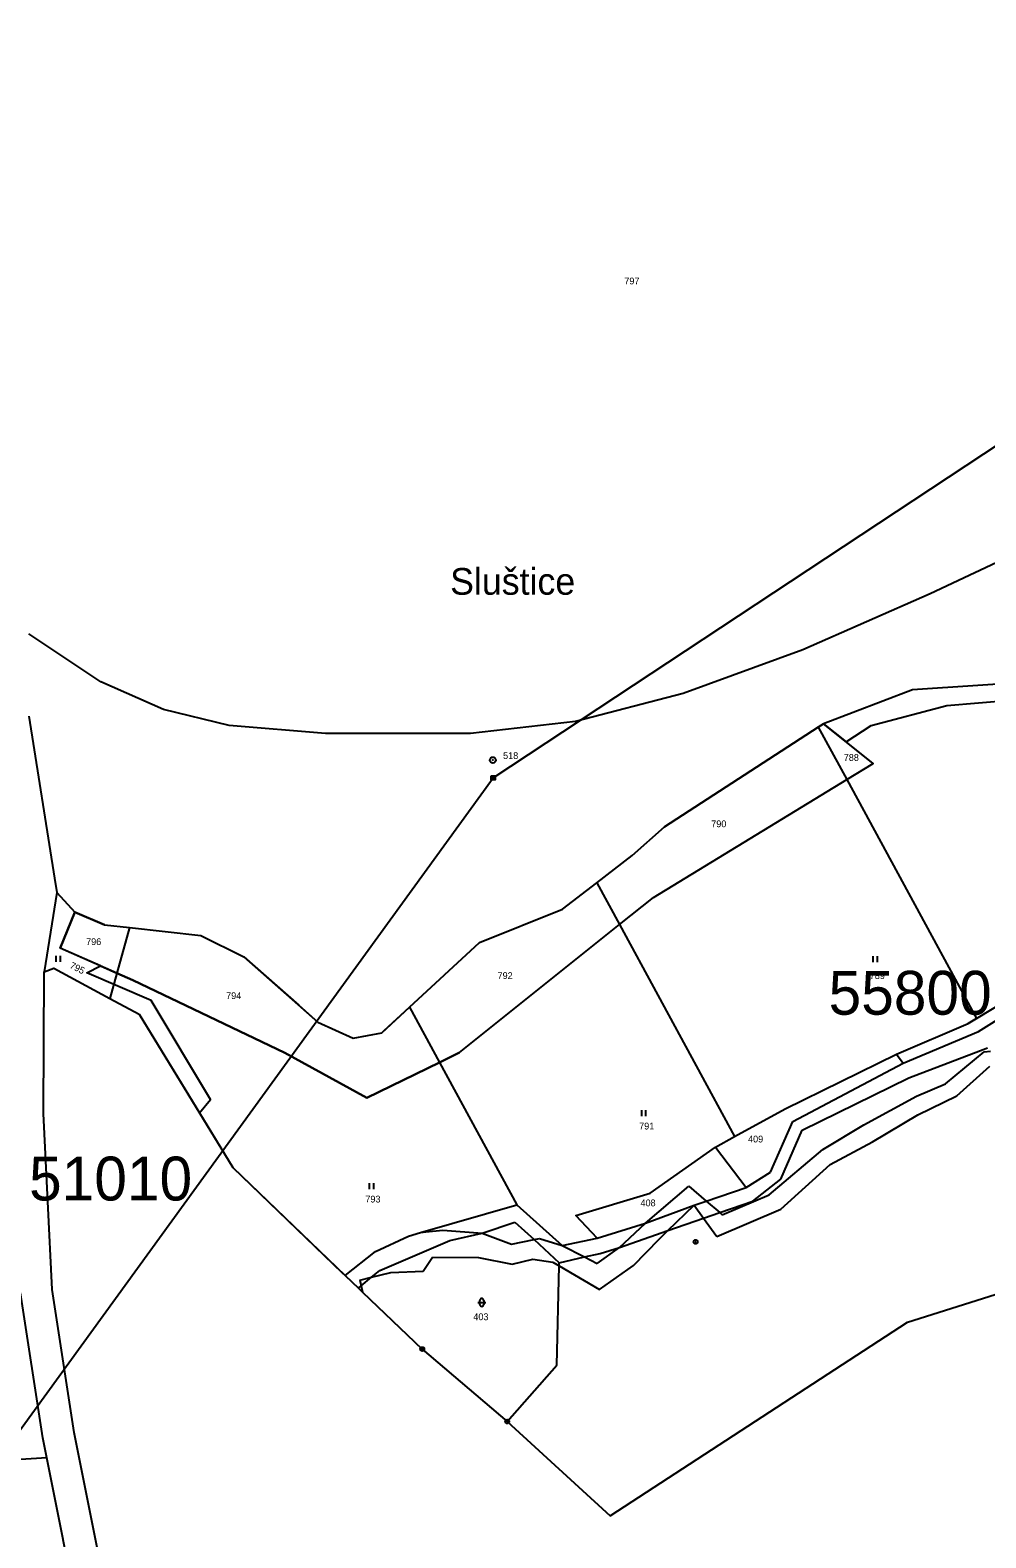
# Model space of a CAD drawing. Extents: x -725765 to -723182, y -1052705 to -1049154.
# Drawn here: x -724181.6 to -723941.9, y -1052292.7 to -1051914.6 of the extents above; entities that cross this region are included whole.
import ezdxf

# ---------------------------------------------------------------- set-up
doc = ezdxf.new("R2010")
doc.units = 0
for name, color, linetype in [('Vrstva 1', 7, 'Continuous'), ('Vrstva 12', 7, 'Continuous'), ('Vrstva 13', 7, 'Continuous'), ('Vrstva 15', 7, 'Continuous'), ('Vrstva 17', 7, 'Continuous'), ('Vrstva 18', 7, 'Continuous'), ('Vrstva 25', 7, 'Continuous'), ('Vrstva 4', 7, 'Continuous'), ('Vrstva 52', 7, 'Continuous'), ('Vrstva 53', 7, 'Continuous')]:
    doc.layers.add(name, color=color, linetype=linetype)

msp = doc.modelspace()

# ---------------------------------------------------------------- linework, layer by layer
at = {"layer": 'Vrstva 1'}
for points in [[(-723908.6, -1052076.65), (-723960.29, -1052080)], [(-723960.29, -1052080), (-723982.59, -1052088.55)], [(-724181.88, -1052086.64), (-724175.49, -1052127.28)], [(-723983.91, -1052089.4), (-724022.48, -1052114.42)], [(-723982.59, -1052088.55), (-723983.91, -1052089.4)], [(-723983.91, -1052089.4), (-723976.76, -1052102.56)], [(-723970.1, -1052098.5), (-723982.59, -1052088.55)], [(-723976.76, -1052102.56), (-723970.1, -1052098.5)], [(-724025.26, -1052132.16), (-723976.76, -1052102.56)], [(-723976.76, -1052102.56), (-723944.23, -1052162.49)], [(-724030.56, -1052121.62), (-724022.48, -1052114.42)], [(-724039.44, -1052128.44), (-724030.56, -1052121.62)], [(-724175.49, -1052127.28), (-724174.89, -1052130.88)], [(-724174.89, -1052130.88), (-724178.03, -1052150.76)], [(-724174.89, -1052130.88), (-724170.32, -1052135.79)], [(-724048.06, -1052135.06), (-724039.44, -1052128.44)], [(-724039.44, -1052128.44), (-724033.74, -1052138.94)], [(-724068.9, -1052143.41), (-724048.06, -1052135.06)], [(-724033.74, -1052138.94), (-724025.26, -1052132.16)], [(-724170.32, -1052135.79), (-724174.06, -1052144.84)], [(-724162.96, -1052138.99), (-724170.32, -1052135.79)], [(-724162.96, -1052138.99), (-724156.69, -1052139.69)], [(-724073.85, -1052171.03), (-724033.74, -1052138.94)], [(-724033.74, -1052138.94), (-724004.89, -1052192.09)], [(-724156.69, -1052139.69), (-724159.82, -1052151.08)], [(-724156.69, -1052139.69), (-724138.76, -1052141.69)], [(-724138.76, -1052141.69), (-724127.94, -1052147.02)], [(-724159.82, -1052151.08), (-724174.06, -1052144.84)], [(-724086.42, -1052159.64), (-724068.9, -1052143.41)], [(-724127.94, -1052147.02), (-724109.38, -1052163.37)], [(-724159.82, -1052151.08), (-724161.57, -1052157.44)], [(-724155.79, -1052152.85), (-724159.82, -1052151.08)], [(-724117.71, -1052171.11), (-724155.79, -1052152.85)], [(-723944.23, -1052162.49), (-723932.21, -1052155.18)], [(-723943.68, -1052165.74), (-723926.84, -1052155.24)], [(-724093.4, -1052166.11), (-724086.42, -1052159.64)], [(-724086.42, -1052159.64), (-724078.9, -1052173.49)], [(-724109.38, -1052163.37), (-724100.53, -1052167.43)], [(-723964.25, -1052171.44), (-723946.29, -1052163.74)], [(-723962.6, -1052173.71), (-723943.68, -1052165.74)], [(-723944.23, -1052162.49), (-723946.29, -1052163.74)], [(-724100.53, -1052167.43), (-724093.4, -1052166.11)], [(-724097.14, -1052182.37), (-724117.71, -1052171.11)], [(-724073.85, -1052171.03), (-724078.9, -1052173.49)], [(-723992.25, -1052185.16), (-723964.25, -1052171.44)], [(-723964.25, -1052171.44), (-723962.6, -1052173.71)], [(-723961.21, -1052177.4), (-723941.45, -1052169.84)], [(-724078.9, -1052173.49), (-724097.14, -1052182.37)], [(-724078.9, -1052173.49), (-724059.51, -1052209.19)], [(-723990.3, -1052188.28), (-723962.6, -1052173.71)], [(-723987.92, -1052190.48), (-723961.21, -1052177.4)], [(-724004.89, -1052192.09), (-723992.25, -1052185.16)], [(-723995.88, -1052201.01), (-723990.3, -1052188.28)], [(-724009.71, -1052194.73), (-724004.89, -1052192.09)], [(-723993.3, -1052202.76), (-723987.92, -1052190.48)], [(-724026.1, -1052206.3), (-724009.71, -1052194.73)], [(-724009.71, -1052194.73), (-724002.02, -1052204.91)], [(-724002.02, -1052204.91), (-723995.88, -1052201.01)], [(-724000.34, -1052208.28), (-723993.3, -1052202.76)], [(-724044.72, -1052211.91), (-724026.1, -1052206.3)], [(-724012.03, -1052208.26), (-724002.02, -1052204.91)], [(-724083.68, -1052216.19), (-724059.51, -1052209.19)], [(-724059.51, -1052209.19), (-724048.17, -1052219.4)], [(-724027.22, -1052213.85), (-724015.05, -1052209.27)], [(-724015.05, -1052209.27), (-724012.03, -1052208.26)], [(-724008.63, -1052211.16), (-724000.34, -1052208.28)], [(-724068.24, -1052216.33), (-724060.04, -1052213.53)], [(-724060.04, -1052213.53), (-724055.19, -1052217.95)], [(-724039.36, -1052217.61), (-724044.72, -1052211.91)], [(-724039.36, -1052217.61), (-724027.22, -1052213.85)], [(-724021.62, -1052215.69), (-724012.67, -1052212.57)], [(-724012.67, -1052212.57), (-724008.63, -1052211.16)], [(-724094.97, -1052220.93), (-724086.67, -1052217.06), (-724083.68, -1052216.19)], [(-724093.88, -1052225.65), (-724076.33, -1052218.2)], [(-724076.33, -1052218.2), (-724068.24, -1052216.33)], [(-724055.19, -1052217.95), (-724048.86, -1052223.74)], [(-724048.17, -1052219.4), (-724039.36, -1052217.61)], [(-724033.76, -1052219.92), (-724021.62, -1052215.69)], [(-724102.57, -1052226.97), (-724094.97, -1052220.93)], [(-724048.86, -1052223.74), (-724042.52, -1052222.3)], [(-724042.52, -1052222.3), (-724038.57, -1052221.4)], [(-724038.57, -1052221.4), (-724033.76, -1052219.92)], [(-724095.93, -1052227.37), (-724093.88, -1052225.65)], [(-724049.47, -1052249.46), (-724048.88, -1052224.49)], [(-724048.88, -1052224.49), (-724048.86, -1052223.74)], [(-724099.24, -1052230.14), (-724098.56, -1052229.57)], [(-724098.56, -1052229.57), (-724095.93, -1052227.37)], [(-724178.37, -1052267.7), (-724184.02, -1052231.3)], [(-724061.93, -1052263.57), (-724049.47, -1052249.46)], [(-724177.37, -1052272.69), (-724178.37, -1052267.7)], [(-724177.37, -1052272.69), (-724251.96, -1052277.46)], [(-724169.19, -1052313.69), (-724177.37, -1052272.69)]]:
    msp.add_lwpolyline(points, dxfattribs=at)
at = {"layer": 'Vrstva 12'}
for points in [[(-724065.44, -1052102.13), (-723775.56, -1051910.67)], [(-724292.54, -1052415.07), (-724065.44, -1052102.13)]]:
    msp.add_lwpolyline(points, dxfattribs=at)
at = {"layer": 'Vrstva 13'}
for points in [[(-724178.03, -1052150.76), (-724175.62, -1052149.86)], [(-724175.62, -1052149.86), (-724161.57, -1052157.44)], [(-724178.24, -1052186.28), (-724178.03, -1052150.76)], [(-724161.57, -1052157.44), (-724154.19, -1052161.42)], [(-724154.19, -1052161.42), (-724130.74, -1052199.84)], [(-724176.05, -1052230.49), (-724178.24, -1052186.28)], [(-724130.74, -1052199.84), (-724102.57, -1052226.97)], [(-723961.49, -1052238.61), (-723842.91, -1052201.16)], [(-724102.57, -1052226.97), (-724099.24, -1052230.14)], [(-724170.49, -1052266.3), (-724176.05, -1052230.49)], [(-724099.24, -1052230.14), (-724098.24, -1052231.09)], [(-724098.24, -1052231.09), (-724083.22, -1052245.39)], [(-724036.11, -1052287.22), (-723961.49, -1052238.61)], [(-724083.22, -1052245.39), (-724061.93, -1052263.57)], [(-724061.93, -1052263.57), (-724036.11, -1052287.22)], [(-724161.39, -1052311.89), (-724170.49, -1052266.3)]]:
    msp.add_lwpolyline(points, dxfattribs=at)
at = {"layer": 'Vrstva 25'}
for points in [[(-724065.94, -1052101.63), (-724064.94, -1052101.63), (-724064.94, -1052102.63), (-724065.94, -1052102.63), (-724065.94, -1052101.63)], [(-724065.74, -1052101.83), (-724065.14, -1052101.83), (-724065.14, -1052102.43), (-724065.74, -1052102.43), (-724065.74, -1052101.83)], [(-724065.54, -1052102.03), (-724065.34, -1052102.03), (-724065.34, -1052102.23), (-724065.54, -1052102.23), (-724065.54, -1052102.03)], [(-724175.01, -1052148.29), (-724175.01, -1052146.79)], [(-724173.97, -1052148.29), (-724173.97, -1052146.79)], [(-723970.11, -1052148.35), (-723970.11, -1052146.85)], [(-723969.07, -1052148.35), (-723969.07, -1052146.85)], [(-724028.17, -1052186.99), (-724028.17, -1052185.49)], [(-724027.13, -1052186.99), (-724027.13, -1052185.49)], [(-724096.45, -1052205.29), (-724096.45, -1052203.79)], [(-724095.41, -1052205.29), (-724095.41, -1052203.79)], [(-724069.3, -1052233.71), (-724067.3, -1052233.71)], [(-724068.8, -1052234.21), (-724068.8, -1052233.21)], [(-724067.8, -1052233.21), (-724067.8, -1052234.21)]]:
    msp.add_lwpolyline(points, dxfattribs=at)
for centre, radius in [((-724065.52, -1052097.66), 0.75), ((-724065.52, -1052097.66), 0.032), ((-724014.66, -1052218.5), 0.5), ((-724014.66, -1052218.5), 0.032), ((-724083.22, -1052245.39), 0.5), ((-724083.22, -1052245.39), 0.032), ((-724061.93, -1052263.57), 0.5), ((-724061.93, -1052263.57), 0.032)]:
    msp.add_circle(centre, radius, dxfattribs=at)
for centre, start, end in [((-724068.3, -1052233.21), 0.101, 180.0014), ((-724068.3, -1052234.21), 180.1024, 0.0029)]:
    msp.add_arc(centre, 0.5, start, end, dxfattribs=at)
at = {"layer": 'Vrstva 4'}
for points in [[(-723951.96, -1052178.84), (-723942.31, -1052170.86)], [(-723942.31, -1052170.86), (-723940.69, -1052170.65)], [(-723949.16, -1052181.88), (-723940.85, -1052174.44)], [(-723959.24, -1052181.92), (-723951.96, -1052178.84)], [(-723972.45, -1052189.16), (-723959.24, -1052181.92)], [(-723958.91, -1052186.64), (-723949.16, -1052181.88)], [(-723970.3, -1052193.38), (-723958.91, -1052186.64)], [(-723982.78, -1052195.36), (-723972.45, -1052189.16)], [(-723996.22, -1052206.67), (-723982.78, -1052195.36)], [(-723980.94, -1052199.13), (-723970.3, -1052193.38)], [(-723993.29, -1052210.32), (-723980.94, -1052199.13)], [(-724027.22, -1052213.85), (-724016.41, -1052204.52)], [(-724016.41, -1052204.52), (-724012.03, -1052208.26)], [(-724007.97, -1052211.73), (-723996.22, -1052206.67)], [(-724021.62, -1052215.69), (-724015.05, -1052209.27)], [(-724015.05, -1052209.27), (-724012.67, -1052212.57)], [(-724012.03, -1052208.26), (-724008.63, -1052211.16)], [(-724009.37, -1052217.17), (-723993.29, -1052210.32)], [(-724033.76, -1052219.92), (-724027.22, -1052213.85)], [(-724012.67, -1052212.57), (-724009.37, -1052217.17)], [(-724008.63, -1052211.16), (-724007.97, -1052211.73)], [(-724083.68, -1052216.19), (-724082.37, -1052216)], [(-724082.37, -1052216), (-724078.06, -1052215.54)], [(-724078.06, -1052215.54), (-724068.24, -1052216.33)], [(-724068.24, -1052216.33), (-724060.84, -1052219.1)], [(-724060.84, -1052219.1), (-724055.19, -1052217.95)], [(-724055.19, -1052217.95), (-724053.79, -1052217.67)], [(-724053.79, -1052217.67), (-724048.17, -1052219.4)], [(-724030.27, -1052224.41), (-724023.82, -1052217.84)], [(-724023.82, -1052217.84), (-724021.62, -1052215.69)], [(-724083, -1052225.82), (-724080.63, -1052222.33)], [(-724080.63, -1052222.33), (-724069.12, -1052222.43)], [(-724069.12, -1052222.43), (-724060.67, -1052224.11)], [(-724048.17, -1052219.4), (-724042.52, -1052222.3)], [(-724042.52, -1052222.3), (-724039.32, -1052223.94)], [(-724039.32, -1052223.94), (-724033.76, -1052219.92)], [(-724095.93, -1052227.37), (-724091.13, -1052226.17)], [(-724091.13, -1052226.17), (-724083, -1052225.82)], [(-724060.67, -1052224.11), (-724055.51, -1052222.82)], [(-724055.51, -1052222.82), (-724050.46, -1052223.56)], [(-724050.46, -1052223.56), (-724048.88, -1052224.49)], [(-724048.88, -1052224.49), (-724038.81, -1052230.42)], [(-724038.81, -1052230.42), (-724030.27, -1052224.41)], [(-724098.87, -1052228.1), (-724095.93, -1052227.37)], [(-724098.87, -1052228.1), (-724098.56, -1052229.57)], [(-724098.56, -1052229.57), (-724098.24, -1052231.09)]]:
    msp.add_lwpolyline(points, dxfattribs=at)
at = {"layer": 'Vrstva 52'}
for points in [[(-723872, -1052064.82), (-723858.63, -1052055), (-723845, -1052045), (-723830.13, -1052028), (-723800.88, -1051981), (-723854.31, -1052009), (-723902.69, -1052031), (-723955.81, -1052056), (-723987.81, -1052070), (-724017.81, -1052081), (-724044.81, -1052088), (-724071.13, -1052091), (-724107.5, -1052091), (-724131.69, -1052089), (-724148.13, -1052085), (-724163.81, -1052078), (-724181.88, -1052066)], [(-724102.57, -1052226.97), (-724094.97, -1052220.93), (-724086.67, -1052217.06), (-724083.68, -1052216.19), (-724059.51, -1052209.19), (-724048.17, -1052219.4), (-724039.36, -1052217.61), (-724044.72, -1052211.91), (-724026.1, -1052206.3), (-724009.71, -1052194.73), (-724004.89, -1052192.09), (-723992.25, -1052185.16), (-723964.25, -1052171.44), (-723946.29, -1052163.74), (-723944.23, -1052162.49), (-723932.21, -1052155.18), (-723914.73, -1052133.27), (-723910.43, -1052116.31), (-723910.94, -1052080), (-723910.23, -1052078.98)], [(-723976.88, -1052093.1), (-723970.63, -1052089), (-723951.69, -1052084), (-723927.81, -1052082), (-723910.23, -1052078.98)], [(-724163.93, -1052149.28), (-724174.06, -1052144.84), (-724170.32, -1052135.79), (-724162.96, -1052138.99), (-724156.69, -1052139.69), (-724138.76, -1052141.69), (-724127.94, -1052147.02), (-724114.15, -1052159.17), (-724109.38, -1052163.37), (-724100.53, -1052167.43), (-724093.4, -1052166.11), (-724092.76, -1052165.51), (-724086.42, -1052159.64), (-724068.9, -1052143.41), (-724048.06, -1052135.06), (-724039.44, -1052128.44), (-724030.56, -1052121.62), (-724022.48, -1052114.42), (-723983.91, -1052089.4), (-723982.59, -1052088.55), (-723976.88, -1052093.1)], [(-724163.93, -1052149.28), (-724159.82, -1052151.08), (-724155.79, -1052152.85), (-724117.71, -1052171.11), (-724097.14, -1052182.37), (-724078.9, -1052173.49), (-724073.85, -1052171.03), (-724033.74, -1052138.94), (-724025.26, -1052132.16), (-723976.76, -1052102.56), (-723970.1, -1052098.5), (-723976.88, -1052093.1)], [(-724375.88, -1052490), (-724358.21, -1052490.13), (-724362.66, -1052398.65), (-724291.38, -1052387.41), (-724234.8, -1052372.78), (-724166.18, -1052360.34), (-724157.63, -1052357.62), (-724149.99, -1052355.2), (-724161.39, -1052311.89), (-724170.49, -1052266.3), (-724176.05, -1052230.49), (-724178.24, -1052186.28), (-724178.03, -1052150.76), (-724175.62, -1052149.86), (-724161.57, -1052157.44), (-724154.19, -1052161.42), (-724139.12, -1052186.12)], [(-724139.12, -1052186.12), (-724136.31, -1052182.78), (-724151.19, -1052158), (-724167.38, -1052151), (-724163.93, -1052149.28)], [(-724139.12, -1052186.12), (-724130.74, -1052199.84), (-724103.29, -1052226.27), (-724102.57, -1052226.97)]]:
    msp.add_lwpolyline(points, dxfattribs=at)

# ---------------------------------------------------------------- texts
at = {"layer": 'Vrstva 15'}
msp.add_text('Sluštice', height=6.7, dxfattribs=at).set_placement((-724076.24, -1052056.19))
at = {"layer": 'Vrstva 17'}
msp.add_text('518 ', height=1.7, dxfattribs=at).set_placement((-724062.95, -1052097.39))
at = {"layer": 'Vrstva 18'}
for s, p in [('797', (-724032.55, -1051978.34)), ('788', (-723977.52, -1052097.86)), ('790', (-724010.75, -1052114.5)), ('796', (-724167.53, -1052144.06)), ('792', (-724064.34, -1052152.57)), ('789', (-723971, -1052152.59)), ('794', (-724132.41, -1052157.6)), ('791', (-724028.83, -1052190.32)), ('409', (-724001.52, -1052193.57)), ('793', (-724097.5, -1052208.63)), ('408', (-724028.49, -1052209.58)), ('403', (-724070.42, -1052238.15))]:
    msp.add_text(s, height=1.7, dxfattribs=at).set_placement(p)
msp.add_text('795', height=1.7, rotation=333.0026, dxfattribs=at).set_placement((-724171.8, -1052149.71))
at = {"layer": 'Vrstva 53'}
for s, p in [('55800', (-723981.32, -1052161.53)), ('51010', (-724181.84, -1052208.13))]:
    msp.add_text(s, height=11, dxfattribs=at).set_placement(p)

doc.saveas('drawing.dxf')
